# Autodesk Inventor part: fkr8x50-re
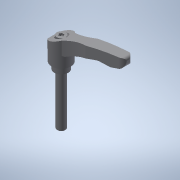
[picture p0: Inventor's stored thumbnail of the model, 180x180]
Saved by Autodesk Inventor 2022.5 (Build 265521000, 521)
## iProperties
Created: 2017-09
Part Number: fkr8x50-re
Material: 一般
Document SubType Name: Modeling
Designer: imaocorp
Density: 1 g/cm^3
Appearance: 既定
Author: imaocorp
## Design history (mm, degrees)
node "fkr8x50-re.x_t1"
node "fkr8x50-re"
node "Base1"
